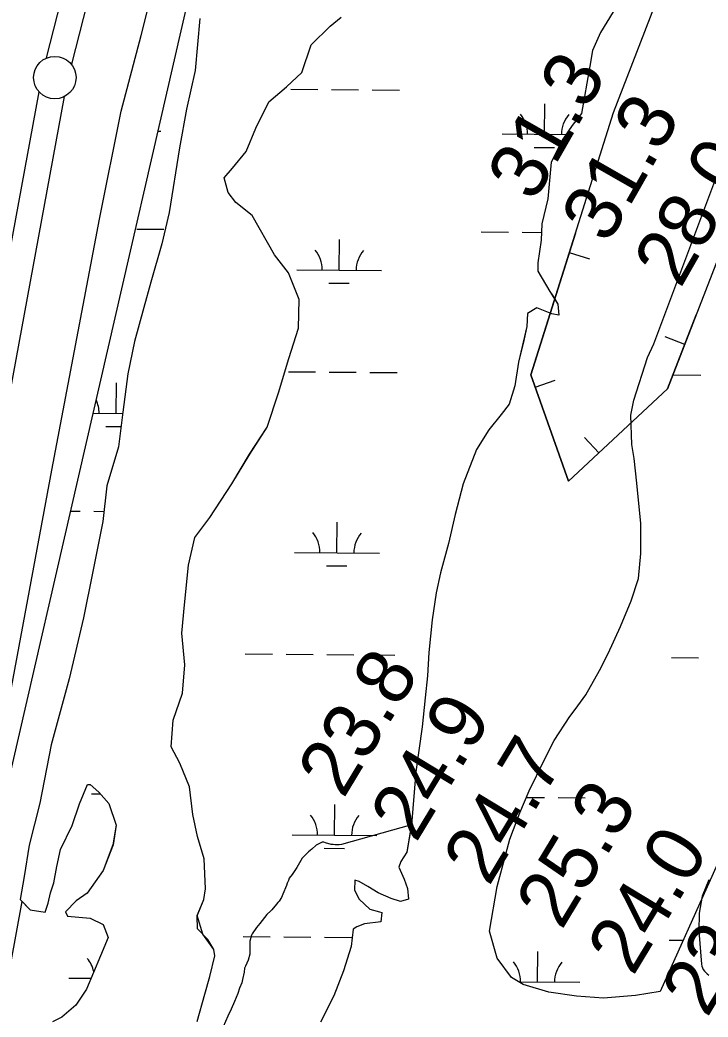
# Model space of a CAD drawing. Extents: x 3271442 to 3309282, y 752266 to 777610.
# Drawn here: x 3286138 to 3286948, y 767918 to 769092 of the extents above; entities that cross this region are included whole.
import ezdxf

# ---------------------------------------------------------------- set-up
doc = ezdxf.new("R2010")
doc.units = 0
for name, color, linetype in [('V-BORW-LINE', 7, 'Continuous'), ('V-LEVE-TOET', 7, 'Continuous'), ('V-RIVR-RANG', 7, 'Continuous'), ('V-SITE-VEGE', 7, 'Continuous'), ('V-SURV-LINE', 7, 'Continuous'), ('V-TOPO-MINR', 7, 'Continuous'), ('V-TOPO-SHOR', 7, 'Continuous'), ('V-WETL-SWMP', 7, 'Continuous')]:
    doc.layers.add(name, color=color, linetype=linetype)

msp = doc.modelspace()

# ---------------------------------------------------------------- linework, layer by layer
at = {"layer": 'V-BORW-LINE'}
for p, q in [((3286784.8, 768818.4), (3286808.6, 768810.8)), ((3286920.8, 768710.1), (3286897.5, 768719.2)), ((3286744.4, 768659.7), (3286768, 768668)), ((3286819.7, 768582.5), (3286802.6, 768600.7))]:
    msp.add_line(p, q, dxfattribs=at)
for points in [[(3287959.8, 771420.8), (3287946.3, 771312), (3287912.3, 771167.5), (3287980.3, 771106.2), (3287939.9, 771015.6), (3287785.1, 770658.1), (3287639, 770330.1), (3287494.9, 770027.9), (3287355.1, 769721.2), (3287167.3, 769303.9), (3286997.6, 768907.9), (3286900.5, 768657.9), (3286783.8, 768549), (3286739.3, 768674.2), (3286836.9, 768983.3), (3286951.6, 769280), (3287086.6, 769683.5), (3287201.4, 769993.4), (3287332, 770288), (3287443.4, 770635.8), (3287581.7, 770941), (3287616.5, 771203.5), (3287625.2, 771250.6)], [(3286791.9, 768841), (3286739.3, 768674.2), (3286783.8, 768549), (3286900.5, 768657.9), (3286934.4, 768745)]]:
    msp.add_lwpolyline(points, dxfattribs=at)
msp.add_spline([(3288895.6, 770368.3), (3288948.3, 770351.6), (3288945.9, 770275), (3288924, 770188.3), (3288802.1, 769884.9), (3288721.3, 769763), (3288606.3, 769551.5), (3288546.8, 769390.6), (3288519.5, 769311.8), (3288413.6, 769096.1), (3288335.4, 768977.4), (3288158.1, 768604.9), (3288099.8, 768456.5), (3288026, 768297.5), (3287981.6, 768216.1), (3287877.7, 767982.7), (3287716.3, 767675.7), (3287537.8, 767414.3), (3287422.2, 767213.6), (3287384.9, 767134.6), (3287323.6, 766984.2), (3287210.2, 766750.6), (3287152.6, 766578.2), (3287021.4, 766252.5), (3286920.2, 766027.8), (3286882.6, 765970.8), (3286824.9, 765909.7), (3286802.9, 765958.5), (3286799.6, 766005.8), (3286860.6, 766282.5), (3286933.4, 766428.6), (3286988.8, 766593.1), (3287018.1, 766670), (3287095, 766821.6), (3287179.4, 766950.5), (3287250.7, 767111.3), (3287335.8, 767252.7), (3287403.7, 767429.9), (3287490.7, 767568.5), (3287565.1, 767720.2), (3287607.6, 767799.9), (3287741.7, 767983.4), (3287810, 768125.6), (3287888.2, 768245.2), (3287960, 768401.3), (3288128.1, 768810.5), (3288156.9, 768885.7), (3288329.3, 769264.9), (3288408.3, 769413.8), (3288665.3, 769952.6), (3288824.1, 770225.2), (3288895.6, 770368.3)], degree=3, dxfattribs=at)
at = {"layer": 'V-LEVE-TOET'}
msp.add_lwpolyline([(3285399.7, 766055.2), (3285445, 766148.2), (3285660, 766605.4), (3285724.8, 766752.3), (3285842.3, 767003), (3285856.6, 767022.9), (3285867.4, 767025.7), (3285881.1, 767029), (3285885.6, 767038.7), (3285888, 767054), (3285886.9, 767069.9), (3285887, 767094.4), (3285892.2, 767117.6), (3285896.3, 767133.5), (3285919.4, 767226.1), (3286015.1, 767705.3), (3286090.6, 768109.6), (3286175.4, 768562.2), (3286231.2, 768857.5), (3286256.7, 768984.7), (3286280.4, 769073.9), (3286345.1, 769332.2)], dxfattribs=at)
at = {"layer": 'V-SITE-VEGE'}
for points in [[(3286836.5, 769101.8), (3286821.6, 769077.4), (3286811.9, 769056.4), (3286808.9, 769037.7), (3286799.1, 768982), (3286788.2, 768967.9), (3286777.3, 768952), (3286763.6, 768924.8), (3286759.4, 768881.6), (3286752.5, 768852.1), (3286751.8, 768832.8), (3286747.8, 768806.1), (3286747.7, 768796.4), (3286761.8, 768772.5), (3286771.4, 768757.7), (3286772.5, 768744.6), (3286764, 768746.3), (3286746.4, 768753.2), (3286735.6, 768746.4), (3286734.9, 768731.1), (3286725.1, 768689.1), (3286720.5, 768661.3), (3286714.1, 768639.7), (3286704.4, 768627.8), (3286690.1, 768609.7), (3286675.3, 768586.4), (3286659.7, 768546.1), (3286650.5, 768509.8), (3286642.4, 768475.7)], [(3286454, 768794.6), (3286437.6, 768815.6), (3286411.1, 768861.8), (3286391.8, 768877.2), (3286382.8, 768889.2), (3286378.3, 768906.2), (3286388, 768917.6), (3286404, 768937.4), (3286415.5, 768964.6), (3286431, 768995.8), (3286451.5, 769013.4), (3286469.8, 769030.3), (3286480.7, 769062.7), (3286502.9, 769084.8), (3286516.1, 769095.5)], [(3286346.4, 767913), (3286355.6, 767945.3), (3286361.4, 767965.8), (3286367.2, 767990.2), (3286366.1, 767997.6), (3286353.2, 768015.7), (3286346.5, 768037.7), (3286354.4, 768056.7), (3286356.2, 768069.2), (3286354.6, 768104.5), (3286346.7, 768130.6), (3286341.2, 768156.8), (3286337.3, 768189.2), (3286326.1, 768217.1), (3286315.9, 768236.5), (3286318.3, 768267.7), (3286329.2, 768299.5), (3286331.7, 768333), (3286328.4, 768370), (3286331.4, 768403.5), (3286336.1, 768450.1), (3286343.6, 768483), (3286361.3, 768506.2), (3286387.1, 768545.9), (3286408.2, 768581.1), (3286428.8, 768612.8), (3286442.1, 768653.1), (3286454.2, 768693.4), (3286465.7, 768729.2), (3286466.4, 768763.2), (3286454, 768794.6)], [(3286642.4, 768475.7), (3286633.2, 768441.1), (3286628, 768417.8), (3286623.3, 768386), (3286619.2, 768347.4), (3286617.9, 768320.1), (3286615, 768294), (3286611.4, 768259.9), (3286603.8, 768207.1), (3286599, 768144.6), (3286516.4, 768121.5), (3286513.5, 768121), (3286509.1, 768121), (3286506.7, 768121.5), (3286504.3, 768121.5), (3286497.5, 768123.5), (3286495.5, 768124), (3286493.6, 768124), (3286490.6, 768122.5), (3286486.7, 768120.6), (3286481.3, 768115.8), (3286477.4, 768112.8), (3286475, 768109.9), (3286471.6, 768107), (3286470.1, 768105.1), (3286463.7, 768094.4), (3286458.3, 768086.1), (3286454.9, 768081.8), (3286453.9, 768078.8), (3286452.4, 768075.9), (3286451.5, 768073), (3286447.5, 768062.8), (3286445.6, 768058.9), (3286443.1, 768054.5), (3286441.6, 768053.1), (3286439.7, 768051.1), (3286434.4, 768044.6), (3286433.3, 768043.4), (3286428.4, 768039), (3286420.1, 768028.3), (3286416.2, 768023.5), (3286411.3, 768016.2), (3286410.3, 768014.7), (3286408.3, 768007.4), (3286408.3, 767992.3), (3286406.3, 767985), (3286404.8, 767981.6), (3286403.3, 767978.2), (3286402.3, 767975.8), (3286401.8, 767970.9), (3286399.9, 767962.6), (3286398.9, 767958.3), (3286396.4, 767952.4), (3286394.4, 767946.1), (3286390.5, 767936.4), (3286386.6, 767927.6), (3286382.6, 767919.3), (3286377.2, 767906.7)], [(3286114.2, 767912.6), (3286140.1, 768054.3), (3286149.8, 768044.5), (3286167.4, 768041.6), (3286170.8, 768052.4), (3286173.7, 768064.3), (3286177.7, 768076.2), (3286181.2, 768095.5), (3286185.3, 768115.4), (3286199, 768143.8), (3286207.7, 768169.3), (3286217.4, 768192), (3286220.3, 768192), (3286230.5, 768182.8), (3286242.3, 768169.7), (3286250.8, 768144.1), (3286247.2, 768120.8), (3286235.8, 768090.8), (3286216.9, 768064.1), (3286203.8, 768055.1), (3286191.2, 768042.1), (3286193.5, 768036.9), (3286220.2, 768034.6), (3286235.5, 768027.1), (3286241.7, 768011.7), (3286232.5, 767990.2), (3286215.9, 767951), (3286203.3, 767932.3), (3286186.8, 767918.2), (3286175.9, 767912.5)]]:
    msp.add_lwpolyline(points, dxfattribs=at)
at = {"layer": 'V-SURV-LINE'}
for points in [[(3286169.1, 769047.4), (3286867.7, 771778.8)], [(3286896.7, 771771.4), (3286198.2, 769040)], [(3285821, 767164.3), (3286160.4, 769007.4)], [(3286189.9, 769002), (3285850.5, 767158.9)]]:
    msp.add_lwpolyline(points, dxfattribs=at)
msp.add_circle((3286178.7, 769024.3), 25, dxfattribs=at)
at = {"layer": 'V-TOPO-MINR'}
for points in [[(3286949.2, 768079.7), (3286941.4, 768060.6)], [(3286941.4, 768060.6), (3286937.9, 768040.4), (3286937.3, 768019.3), (3286940.5, 767980.6), (3286940.9, 767978.3), (3286941.5, 767976.1), (3286942.6, 767974.1), (3286943.9, 767972.2), (3286945.5, 767970.5), (3286947.2, 767968.9), (3286949.1, 767967.5)]]:
    msp.add_lwpolyline(points, dxfattribs=at)
at = {"layer": 'V-TOPO-SHOR'}
for points in [[(3286836.5, 769101.8), (3286821.6, 769077.4), (3286811.9, 769056.4), (3286808.9, 769037.7), (3286799.1, 768982), (3286788.2, 768967.9), (3286777.3, 768952), (3286763.6, 768924.8), (3286759.4, 768881.6), (3286752.5, 768852.1), (3286751.8, 768832.8), (3286747.8, 768806.1), (3286747.7, 768796.4), (3286761.8, 768772.5), (3286765.2, 768767.4), (3286771.4, 768757.7), (3286772.5, 768744.6), (3286764, 768746.3), (3286746.4, 768753.2), (3286735.6, 768746.4), (3286734.9, 768731.1), (3286730.3, 768711.2), (3286725.1, 768689.1), (3286720.5, 768661.3), (3286714.1, 768639.7), (3286704.4, 768627.8), (3286690.1, 768609.7), (3286675.3, 768586.4), (3286659.7, 768546.1)], [(3286349.5, 769093.9), (3286344.2, 769032.6), (3286333.8, 768987.1), (3286325.6, 768941.7), (3286313.4, 768865.6), (3286304.7, 768828.7), (3286292, 768783.3), (3286283.4, 768753.8), (3286272.4, 768713.5), (3286264.9, 768675.4), (3286259, 768630.5), (3286253.7, 768589.6), (3286239.9, 768543.7), (3286235.2, 768501.6), (3286223.6, 768442.6), (3286212.5, 768388.1), (3286195.8, 768316.5), (3286174.4, 768238.8), (3286161.1, 768170), (3286148.4, 768120.7), (3286142.5, 768083.7), (3286137.9, 768056.5), (3286149.8, 768044.5), (3286167.4, 768041.6), (3286170.8, 768052.4), (3286173.7, 768064.3), (3286177.7, 768076.2), (3286181.2, 768095.5), (3286185.3, 768115.4), (3286199, 768143.8), (3286207.7, 768169.3), (3286217.4, 768192), (3286220.3, 768192), (3286230.5, 768182.8), (3286242.3, 768169.7), (3286250.8, 768144.1), (3286247.2, 768120.8), (3286235.8, 768090.8), (3286216.9, 768064.1), (3286203.8, 768055.1), (3286191.2, 768042.1), (3286193.5, 768036.9), (3286220.2, 768034.6), (3286235.5, 768027.1), (3286241.7, 768011.7), (3286232.5, 767990.2), (3286215.9, 767951), (3286203.3, 767932.3), (3286186.8, 767918.2), (3286175.9, 767912.5)], [(3286346.4, 767913), (3286355.6, 767945.3), (3286361.4, 767965.8), (3286367.2, 767990.2), (3286366.1, 767997.6), (3286358.8, 768009.5), (3286346.9, 768022.1), (3286346.4, 768037.4), (3286354.4, 768056.7), (3286356.2, 768069.2), (3286354.6, 768104.5), (3286346.7, 768130.6), (3286341.2, 768156.8), (3286337.3, 768189.2), (3286326.1, 768217.1), (3286315.9, 768236.5), (3286318.3, 768267.7), (3286329.2, 768299.5), (3286331.7, 768333), (3286328.4, 768370), (3286331.4, 768403.5), (3286336.1, 768450.1), (3286343.6, 768483), (3286361.3, 768506.2), (3286387.1, 768545.9), (3286408.2, 768581.1), (3286428.8, 768612.8), (3286442.1, 768653.1), (3286454.2, 768693.4), (3286465.7, 768729.2), (3286466.4, 768763.2), (3286454, 768794.6), (3286437.6, 768815.6), (3286411.1, 768861.8), (3286391.8, 768877.2), (3286382.8, 768889.2), (3286378.3, 768906.2), (3286388, 768917.6), (3286404, 768937.4), (3286415.5, 768964.6), (3286431, 768995.8), (3286451.5, 769013.4), (3286469.8, 769030.3), (3286480.7, 769062.7), (3286502.9, 769084.8), (3286516.1, 769095.5)], [(3286659.7, 768546.1), (3286650.5, 768509.8), (3286642.4, 768475.7), (3286633.2, 768441.1), (3286628, 768417.8), (3286623.3, 768386), (3286619.2, 768347.4), (3286617.9, 768320.1), (3286615, 768294), (3286611.4, 768259.9), (3286603.8, 768207.1), (3286599, 768144.6), (3286596.7, 768131.5), (3286593.2, 768112.2), (3286586.3, 768101.5), (3286584, 768094.7), (3286590.2, 768080.4), (3286594.2, 768069.6), (3286595.2, 768057.1), (3286586.1, 768054.3), (3286574.8, 768057.8), (3286559.5, 768064.6), (3286547.6, 768072.1), (3286537.4, 768077.8), (3286532.2, 768079.5), (3286531.6, 768067.6), (3286537.3, 768056.8), (3286549.7, 768045.4), (3286561.1, 768041.9), (3286563.9, 768041.3), (3286562.7, 768030.5), (3286543.4, 768027.8), (3286534.3, 768024.4), (3286530.3, 768021.6), (3286527.9, 768001.1), (3286518.7, 767972.7), (3286507.3, 767943.2), (3286491.8, 767912)]]:
    msp.add_lwpolyline(points, dxfattribs=at)
at = {"layer": 'V-WETL-SWMP'}
for p, q in [((3286096.6, 768076.4), (3286586.9, 770206.2)), ((3286836.5, 769101.8), (3286821.6, 769077.4)), ((3286349.5, 769093.9), (3286344.2, 769032.6)), ((3286502.9, 769084.8), (3286516.1, 769095.5)), ((3286480.7, 769062.7), (3286502.9, 769084.8)), ((3286821.6, 769077.4), (3286811.9, 769056.4)), ((3286469.8, 769030.3), (3286480.7, 769062.7)), ((3286811.9, 769056.4), (3286808.9, 769037.7)), ((3286344.2, 769032.6), (3286333.8, 768987.1)), ((3286451.5, 769013.4), (3286469.8, 769030.3)), ((3286808.9, 769037.7), (3286799.1, 768982)), ((3286431, 768995.8), (3286451.5, 769013.4)), ((3286456.6, 769010.7), (3286488.6, 769010.4)), ((3286504.6, 769010.3), (3286536.6, 769010)), ((3286552.6, 769009.9), (3286584.6, 769009.6)), ((3286415.5, 768964.6), (3286431, 768995.8)), ((3286755.5, 768957.5), (3286755.8, 768993.5)), ((3286333.8, 768987.1), (3286325.6, 768941.7)), ((3286799.1, 768982), (3286788.2, 768967.9)), ((3286788.2, 768967.9), (3286777.3, 768952)), ((3286300.3, 768961.2), (3286303.6, 768961.2)), ((3286404, 768937.4), (3286415.5, 768964.6)), ((3286705.5, 768957.9), (3286780.9, 768957.3)), ((3286884.3, 768710.8), (3286976.9, 768957.9)), ((3286777.3, 768952), (3286763.6, 768924.8)), ((3286325.6, 768941.7), (3286313.4, 768865.6)), ((3286388, 768917.6), (3286404, 768937.4)), ((3286743.4, 768942.1), (3286767.4, 768941.9)), ((3286763.6, 768924.8), (3286759.4, 768881.6)), ((3286378.3, 768906.2), (3286388, 768917.6)), ((3286382.8, 768889.2), (3286378.3, 768906.2)), ((3286391.8, 768877.2), (3286382.8, 768889.2)), ((3286411.1, 768861.8), (3286391.8, 768877.2)), ((3286759.4, 768881.6), (3286752.5, 768852.1)), ((3286313.4, 768865.6), (3286304.7, 768828.7)), ((3286437.6, 768815.6), (3286411.1, 768861.8)), ((3286752.5, 768852.1), (3286751.8, 768832.8)), ((3286275.2, 768846), (3286307.2, 768845.7)), ((3286681.1, 768842.6), (3286713.1, 768842.4)), ((3286729.1, 768842.2), (3286752.2, 768842.1)), ((3286304.7, 768828.7), (3286292, 768783.3)), ((3286513.7, 768797.6), (3286514, 768833.6)), ((3286751.8, 768832.8), (3286747.8, 768806.1)), ((3286454, 768794.6), (3286437.6, 768815.6)), ((3286747.8, 768806.1), (3286747.7, 768796.4)), ((3286466.4, 768763.2), (3286454, 768794.6)), ((3286463.7, 768798), (3286563.7, 768797.2)), ((3286747.7, 768796.4), (3286761.8, 768772.5)), ((3286292, 768783.3), (3286283.4, 768753.8)), ((3286501.6, 768782.3), (3286525.6, 768782.1)), ((3286761.8, 768772.5), (3286771.4, 768757.7)), ((3286465.7, 768729.2), (3286466.4, 768763.2)), ((3286771.4, 768757.7), (3286772.5, 768744.6)), ((3286283.4, 768753.8), (3286272.4, 768713.5)), ((3286735.6, 768746.4), (3286734.9, 768731.1)), ((3286746.4, 768753.2), (3286735.6, 768746.4)), ((3286764, 768746.3), (3286746.4, 768753.2)), ((3286772.5, 768744.6), (3286764, 768746.3)), ((3286454.2, 768693.4), (3286465.7, 768729.2)), ((3286734.9, 768731.1), (3286725.1, 768689.1)), ((3286272.4, 768713.5), (3286264.9, 768675.4)), ((3286876.7, 768694.9), (3286884.3, 768710.8)), ((3286442.1, 768653.1), (3286454.2, 768693.4)), ((3286725.1, 768689.1), (3286720.5, 768661.3)), ((3286860.6, 768644.7), (3286876.7, 768694.9)), ((3286264.9, 768675.4), (3286259, 768630.5)), ((3286453.9, 768678), (3286485.9, 768677.7)), ((3286501.9, 768677.6), (3286533.9, 768677.3)), ((3286549.9, 768677.2), (3286581.9, 768676.9)), ((3286907.8, 768674.3), (3286939.8, 768674)), ((3286250.9, 768628.9), (3286251.2, 768664.9)), ((3286428.8, 768612.8), (3286442.1, 768653.1)), ((3286720.5, 768661.3), (3286714.1, 768639.7)), ((3286714.1, 768639.7), (3286704.4, 768627.8)), ((3286857.1, 768626.8), (3286860.6, 768644.7)), ((3286223.9, 768629.2), (3286258.8, 768628.9)), ((3286259, 768630.5), (3286253.7, 768589.6)), ((3286704.4, 768627.8), (3286690.1, 768609.7)), ((3286858.4, 768592.3), (3286857.1, 768626.8)), ((3286238.7, 768613.6), (3286256.8, 768613.5)), ((3286408.3, 768581.1), (3286428.8, 768612.8)), ((3286690.1, 768609.7), (3286675.3, 768586.4)), ((3286861.1, 768575.8), (3286858.4, 768592.3)), ((3286253.7, 768589.6), (3286239.9, 768543.7)), ((3286387.1, 768545.9), (3286408.3, 768581.1)), ((3286675.3, 768586.4), (3286659.7, 768546.1)), ((3286864.4, 768546.8), (3286861.1, 768575.8)), ((3286361.3, 768506.2), (3286387.1, 768545.9)), ((3286659.7, 768546.1), (3286650.5, 768509.8)), ((3286869.1, 768499.2), (3286864.4, 768546.8)), ((3286239.9, 768543.7), (3286235.2, 768501.6)), ((3286197.3, 768513.9), (3286208.5, 768513.8)), ((3286224.5, 768513.7), (3286236.5, 768513.6)), ((3286650.5, 768509.8), (3286642.4, 768475.7)), ((3286235.2, 768501.6), (3286223.6, 768442.6)), ((3286343.6, 768483), (3286361.3, 768506.2)), ((3286511, 768464.9), (3286511.2, 768500.9)), ((3286868.9, 768464.1), (3286869.1, 768499.2)), ((3286336.1, 768450.1), (3286343.6, 768483)), ((3286642.4, 768475.7), (3286633.2, 768441.1)), ((3286461, 768465.3), (3286561, 768464.5)), ((3286866.1, 768434.4), (3286868.9, 768464.1)), ((3286223.6, 768442.6), (3286212.5, 768388.1)), ((3286331.4, 768403.5), (3286336.1, 768450.1)), ((3286498.8, 768449.6), (3286522.8, 768449.4)), ((3286633.2, 768441.1), (3286628, 768417.8)), ((3286857.7, 768408.3), (3286866.1, 768434.4)), ((3286628, 768417.8), (3286623.3, 768386)), ((3286845.2, 768378), (3286857.7, 768408.3)), ((3286328.4, 768370), (3286331.4, 768403.5)), ((3286212.5, 768388.1), (3286195.8, 768316.5)), ((3286623.3, 768386), (3286619.2, 768347.4)), ((3286331.7, 768333), (3286328.4, 768370)), ((3286830.6, 768346.4), (3286845.2, 768378)), ((3286403.1, 768345.7), (3286435.1, 768345.5)), ((3286451.1, 768345.3), (3286483.1, 768345.1)), ((3286619.2, 768347.4), (3286617.9, 768320.1)), ((3286820.2, 768326.4), (3286830.6, 768346.4)), ((3286499.1, 768344.9), (3286531.1, 768344.7)), ((3286547.1, 768344.5), (3286579.1, 768344.3)), ((3286905, 768341.6), (3286937, 768341.3)), ((3286329.2, 768299.5), (3286331.7, 768333)), ((3286804.2, 768297.5), (3286820.2, 768326.4)), ((3286195.8, 768316.5), (3286174.4, 768238.8)), ((3286617.9, 768320.1), (3286615, 768294)), ((3286318.3, 768267.7), (3286329.2, 768299.5)), ((3286615, 768294), (3286611.4, 768259.9)), ((3286791.7, 768280.3), (3286804.2, 768297.5)), ((3286800, 768291.7), (3286800, 768291.7)), ((3286785.5, 768272.1), (3286791.7, 768280.3)), ((3286315.9, 768236.5), (3286318.3, 768267.7)), ((3286766.8, 768243.9), (3286785.5, 768272.1)), ((3286611.4, 768259.9), (3286603.8, 768207.1)), ((3286755, 768220.5), (3286766.8, 768243.9)), ((3286174.4, 768238.8), (3286161.1, 768170)), ((3286326.1, 768217.1), (3286315.9, 768236.5)), ((3286337.3, 768189.2), (3286326.1, 768217.1)), ((3286737.6, 768184.7), (3286755, 768220.5)), ((3286603.8, 768207.1), (3286599, 768144.6)), ((3286207.7, 768169.3), (3286217.4, 768192)), ((3286217.4, 768192), (3286220.3, 768192)), ((3286220.3, 768192), (3286230.5, 768182.8)), ((3286221.8, 768181.1), (3286232.2, 768181)), ((3286230.5, 768182.8), (3286242.3, 768169.7)), ((3286341.2, 768156.8), (3286337.3, 768189.2)), ((3286726.5, 768158.6), (3286737.6, 768184.7)), ((3286161.1, 768170), (3286148.4, 768120.7)), ((3286199, 768143.8), (3286207.7, 768169.3)), ((3286242.3, 768169.7), (3286250.8, 768144.1)), ((3286734.2, 768176.8), (3286755.6, 768176.7)), ((3286771.6, 768176.5), (3286803.6, 768176.3)), ((3286508.2, 768132.3), (3286508.5, 768168.3)), ((3286714.6, 768127.6), (3286726.5, 768158.6)), ((3286346.7, 768130.6), (3286341.2, 768156.8)), ((3286982.8, 768151.4), (3286891.8, 767948.4)), ((3286185.3, 768115.4), (3286199, 768143.8)), ((3286250.8, 768144.1), (3286247.3, 768120.8)), ((3286599, 768144.6), (3286593.2, 768112.2)), ((3286354.6, 768104.5), (3286346.7, 768130.6)), ((3286458.2, 768132.7), (3286558.2, 768131.8)), ((3286699.9, 768071.8), (3286714.6, 768127.6)), ((3286148.4, 768120.7), (3286142.5, 768083.7)), ((3286181.2, 768095.5), (3286185.3, 768115.4)), ((3286247.3, 768120.8), (3286235.8, 768090.8)), ((3286496.1, 768116.9), (3286520.1, 768116.7)), ((3286593.2, 768112.2), (3286586.3, 768101.5)), ((3286356.2, 768069.2), (3286354.6, 768104.5)), ((3286586.3, 768101.5), (3286584, 768094.7)), ((3286177.7, 768076.2), (3286181.2, 768095.5)), ((3286235.8, 768090.8), (3286216.9, 768064.1)), ((3286584, 768094.7), (3286590.2, 768080.4)), ((3286142.5, 768083.7), (3286137.9, 768056.5)), ((3286173.7, 768064.3), (3286177.7, 768076.2)), ((3286532.2, 768079.5), (3286531.6, 768067.6)), ((3286537.4, 768077.8), (3286532.2, 768079.5)), ((3286547.6, 768072.1), (3286537.4, 768077.8)), ((3286590.2, 768080.4), (3286594.2, 768069.6)), ((3286170.8, 768052.4), (3286173.7, 768064.3)), ((3286216.9, 768064.1), (3286203.8, 768055.1)), ((3286354.4, 768056.7), (3286356.2, 768069.2)), ((3286531.6, 768067.6), (3286537.3, 768056.8)), ((3286559.5, 768064.6), (3286547.6, 768072.1)), ((3286574.8, 768057.8), (3286559.5, 768064.6)), ((3286594.2, 768069.6), (3286595.2, 768057.1)), ((3286690.8, 768019.5), (3286699.9, 768071.8)), ((3286137.9, 768056.5), (3286149.8, 768044.5)), ((3286167.4, 768041.6), (3286170.8, 768052.4)), ((3286203.8, 768055.1), (3286191.2, 768042.1)), ((3286346.4, 768037.4), (3286354.4, 768056.7)), ((3286537.3, 768056.8), (3286549.7, 768045.4)), ((3286586.1, 768054.3), (3286574.8, 768057.8)), ((3286595.2, 768057.1), (3286586.1, 768054.3)), ((3286149.8, 768044.5), (3286167.4, 768041.6)), ((3286191.2, 768042.1), (3286193.5, 768036.9)), ((3286549.7, 768045.4), (3286561.1, 768041.9)), ((3286561.1, 768041.9), (3286563.9, 768041.3)), ((3286563.9, 768041.3), (3286562.7, 768030.5)), ((3286193.5, 768036.9), (3286220.2, 768034.6)), ((3286220.2, 768034.6), (3286235.5, 768027.1)), ((3286346.9, 768022.1), (3286346.4, 768037.4)), ((3286562.7, 768030.5), (3286543.4, 768027.8)), ((3286235.5, 768027.1), (3286241.7, 768011.7)), ((3286358.8, 768009.6), (3286346.9, 768022.1)), ((3286530.3, 768021.6), (3286527.9, 768001.1)), ((3286534.3, 768024.4), (3286530.3, 768021.6)), ((3286543.4, 768027.8), (3286534.3, 768024.4)), ((3286699.6, 767987.7), (3286690.8, 768019.5)), ((3286241.7, 768011.7), (3286232.5, 767990.2)), ((3286366.1, 767997.6), (3286358.8, 768009.6)), ((3286400.4, 768013.1), (3286432.4, 768012.8)), ((3286448.4, 768012.7), (3286480.4, 768012.4)), ((3286496.4, 768012.3), (3286528.4, 768012)), ((3286902.3, 768008.9), (3286918.9, 768008.8)), ((3286367.2, 767990.2), (3286366.1, 767997.6)), ((3286527.9, 768001.1), (3286518.7, 767972.7)), ((3286747.3, 767959.5), (3286747.6, 767995.5)), ((3286232.5, 767990.2), (3286215.9, 767951)), ((3286361.4, 767965.8), (3286367.2, 767990.2)), ((3286716.8, 767964.9), (3286699.6, 767987.7)), ((3286518.7, 767972.7), (3286507.3, 767943.2)), ((3286195.4, 767964), (3286221.3, 767963.8)), ((3286355.6, 767945.3), (3286361.4, 767965.8)), ((3286730.5, 767956.6), (3286716.8, 767964.9)), ((3286725.5, 767959.7), (3286797.3, 767959.1)), ((3286215.9, 767951), (3286203.3, 767932.3)), ((3286760.8, 767947.5), (3286730.5, 767956.6)), ((3286793.2, 767942.6), (3286760.8, 767947.5)), ((3286891.8, 767948.4), (3286862.8, 767943.7)), ((3286346.4, 767913), (3286355.6, 767945.3)), ((3286507.3, 767943.2), (3286491.8, 767912)), ((3286824.9, 767940.4), (3286793.2, 767942.6)), ((3286862.8, 767943.7), (3286824.9, 767940.4)), ((3286203.3, 767932.3), (3286186.8, 767918.2))]:
    msp.add_line(p, q, dxfattribs=at)
for centre, start, end in [((3286700.3, 768958.4), 358.7563, 40.2999), ((3286810.7, 768957.5), 138.7563, 180.2999), ((3286458.5, 768798.5), 358.7563, 40.2999), ((3286568.9, 768797.6), 138.7563, 180.2999), ((3286195.6, 768629.9), 358.7563, 25.285), ((3286455.7, 768465.9), 358.7563, 40.2999), ((3286566.2, 768464.9), 138.7563, 180.2999), ((3286453, 768133.2), 358.7563, 40.2999), ((3286563.5, 768132.3), 138.7563, 180.2999), ((3286190.1, 767964.5), 11.7138, 40.2999), ((3286692, 767960.4), 358.7563, 40.2999), ((3286802.5, 767959.5), 138.7563, 180.2999)]:
    msp.add_arc(centre, 35.2, start, end, dxfattribs=at)

# ---------------------------------------------------------------- texts
at = {"layer": 'V-RIVR-RANG'}
for s, rotation, p in [('31.3', 60.2783, (3286743.1, 768876.3)), ('31.3', 60.2783, (3286830.1, 768826.9)), ('28.0', 60.2783, (3286915.6, 768775)), ('23.8', 58.8083, (3286518.6, 768174.2)), ('24.9', 58.8083, (3286604.1, 768122.3)), ('24.7', 58.8083, (3286689.9, 768071)), ('25.3', 58.8083, (3286775.6, 768019.4)), ('24.0', 58.8083, (3286859.8, 767965.3)), ('23.2', 58.8083, (3286946.9, 767916.2))]:
    msp.add_text(s, height=67, rotation=rotation, dxfattribs=at).set_placement(p)

doc.saveas('drawing.dxf')
